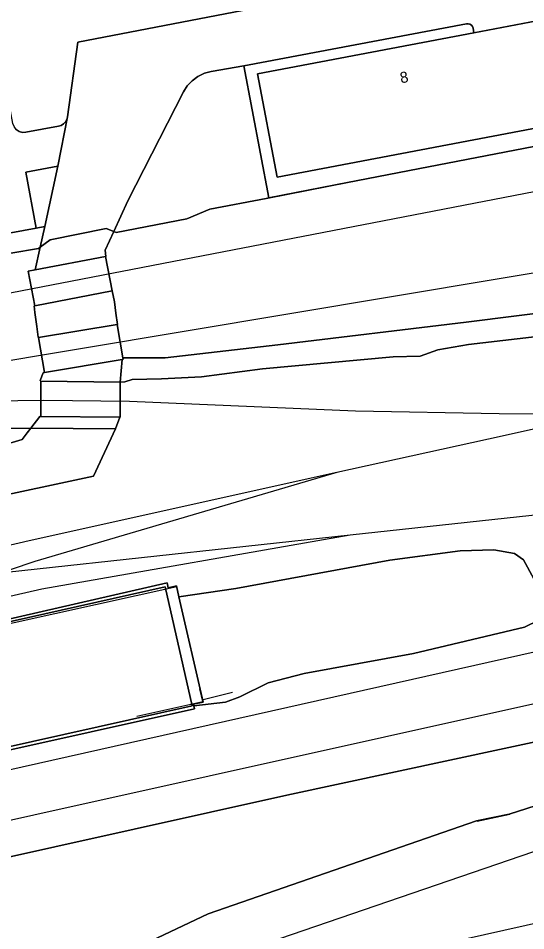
# Model space of a CAD drawing. Extents: x 161477 to 163040, y 383680 to 384871.
# Drawn here: x 161762.8 to 161808.8, y 383823.4 to 383906.2 of the extents above; entities that cross this region are included whole.
import ezdxf

# ---------------------------------------------------------------- set-up
doc = ezdxf.new("R2010")
doc.units = 0
for name, color, linetype in [('IMGEO_Erf', 7, 'Continuous'), ('IMGEO_Groenvoorziening', 7, 'Continuous'), ('IMGEO_Hek', 7, 'Continuous'), ('IMGEO_Overweg_gesloten', 7, 'Continuous'), ('IMGEO_Pand', 7, 'Continuous'), ('IMGEO_Pand_nummerreeks', 7, 'Continuous'), ('IMGEO_Rijbaan_lokaal_open', 7, 'Continuous'), ('IMGEO_Spoor', 7, 'Continuous'), ('IMGEO_Spoorbaan_halfverhard', 7, 'Continuous'), ('IMGEO_Terreindeel_halfverhard', 7, 'Continuous'), ('IMGEO_Terreindeel_onvherhard', 7, 'Continuous'), ('IMGEO_Terreindeel_open', 7, 'Continuous'), ('IMGEO_Voetpad_open', 7, 'Continuous')]:
    doc.layers.add(name, color=color, linetype=linetype)

msp = doc.modelspace()

# ---------------------------------------------------------------- linework, layer by layer
at = {"layer": 'IMGEO_Erf'}
msp.add_lwpolyline([(161767.236, 383897.259), (161767.174, 383897.026), (161767.051, 383896.805), (161766.874, 383896.62), (161766.66, 383896.487), (161766.43, 383896.415), (161763.462, 383895.858), (161763.165, 383895.847), (161762.856, 383895.934), (161762.584, 383896.12), (161762.392, 383896.376), (161762.294, 383896.657), (161761.349, 383901.699), (161722.371, 383894.524), (161723.464, 383887.761), (161723.688, 383886.379), (161724.738, 383879.878), (161764.405, 383887.161), (161763.458, 383892.256), (161766.369, 383892.797)], close=True, dxfattribs=at)
at = {"layer": 'IMGEO_Groenvoorziening'}
msp.add_lwpolyline([(161762.584, 383896.12), (161762.856, 383895.934), (161763.165, 383895.847), (161763.462, 383895.858), (161766.43, 383896.415), (161766.66, 383896.487), (161766.874, 383896.62), (161767.051, 383896.805), (161767.174, 383897.026), (161767.236, 383897.259), (161768.191, 383904.054), (161805.301, 383911.22)], dxfattribs=at)
for points in [[(161785.514, 383889.906), (161783.238, 383901.895), (161780.285, 383901.383), (161779.67, 383901.218), (161779.081, 383900.935), (161778.55, 383900.543), (161778.105, 383900.064), (161777.765, 383899.525), (161772.727, 383889.643), (161771.445, 383886.853), (161771.671, 383886.768), (161778.078, 383888.005), (161780.165, 383888.875), (161785.283, 383889.861)], [(161765.176, 383887.303), (161764.405, 383887.161), (161724.738, 383879.878), (161723.688, 383886.379), (161722.971, 383886.245), (161716.299, 383884.995), (161716.246, 383885.278), (161715.329, 383885.106), (161716.52, 383877.272), (161722.035, 383878.5), (161722.078, 383878.305), (161733.201, 383880.57), (161733.173, 383880.718), (161759.825, 383885.639), (161762.093, 383884.874), (161764.602, 383885.314), (161764.771, 383885.439)]]:
    msp.add_lwpolyline(points, close=True, dxfattribs=at)
at = {"layer": 'IMGEO_Hek'}
for points in [[(161722.078, 383878.305), (161733.201, 383880.57), (161733.173, 383880.718), (161759.825, 383885.639), (161762.093, 383884.874), (161764.602, 383885.314), (161764.771, 383885.439), (161765.685, 383886.113), (161770.75, 383887.114), (161771.445, 383886.853), (161771.671, 383886.768), (161778.078, 383888.005), (161780.165, 383888.875), (161785.283, 383889.861), (161792.641, 383891.294), (161800.007, 383892.712), (161812.228, 383895.079), (161824.037, 383897.352)], [(161729.828, 383842.456), (161729.416, 383844.078), (161732.581, 383844.772), (161777.154, 383854.64)], [(161773.549, 383842.85), (161779.526, 383844.173), (161779.263, 383845.35)], [(161782.207, 383845.009), (161779.557, 383844.346)], [(161804.433, 383833.315), (161807.374, 383833.945)]]:
    msp.add_lwpolyline(points, dxfattribs=at)
at = {"layer": 'IMGEO_Overweg_gesloten'}
for points in [[(161764.322, 383883.369), (161763.665, 383883.243), (161764.27, 383880.1), (161771.309, 383881.454), (161770.704, 383884.597)], [(161771.759, 383878.4), (161764.625, 383877.218), (161765.165, 383874.05), (161772.192, 383875.249), (161772.294, 383875.266), (161772.275, 383875.377)], [(161772.009, 383869.987), (161772.035, 383873.175), (161764.837, 383873.281), (161764.81, 383870.045), (161771.994, 383869.987)]]:
    msp.add_lwpolyline(points, close=True, dxfattribs=at)
at = {"layer": 'IMGEO_Pand'}
for points in [[(161804.125, 383904.891), (161784.496, 383901.165), (161786.276, 383891.788), (161823.722, 383898.897), (161822.28, 383906.491), (161810.184, 383904.195), (161809.846, 383905.977)], [(161778.557, 383843.801), (161776.109, 383854.605), (161755.704, 383850.023), (161755.755, 383849.764), (161732.215, 383844.538), (161734.605, 383834.247), (161758.264, 383839.562), (161758.339, 383839.278)]]:
    msp.add_lwpolyline(points, close=True, dxfattribs=at)
at = {"layer": 'IMGEO_Rijbaan_lokaal_open'}
msp.add_lwpolyline([(161805.301, 383911.22), (161768.191, 383904.054), (161767.236, 383897.259), (161766.369, 383892.797), (161765.176, 383887.303), (161764.771, 383885.439), (161765.685, 383886.113), (161770.75, 383887.114), (161771.445, 383886.853), (161772.727, 383889.643), (161777.765, 383899.525), (161778.105, 383900.064), (161778.55, 383900.543), (161779.081, 383900.935), (161779.67, 383901.218), (161780.285, 383901.383), (161783.238, 383901.895), (161803.46, 383905.713), (161803.609, 383905.719), (161803.763, 383905.676), (161803.899, 383905.583), (161803.996, 383905.455), (161804.045, 383905.315), (161804.125, 383904.891), (161809.846, 383905.977)], dxfattribs=at)
at = {"layer": 'IMGEO_Spoor'}
for points in [[(162082.223, 383940.616), (162067.156, 383939.077), (162060.654, 383938.31), (162050.143, 383936.843), (162039.55, 383934.981), (161761.259, 383881.105), (161737.229, 383876.551), (161717.526, 383872.756)], [(161940.49, 383907.276), (161906.48, 383899.966), (161883.869, 383895.635), (161863.414, 383892.09), (161749.217, 383872.993)], [(162080.398, 383888.27), (162044.958, 383880.311), (162029.101, 383876.523), (161994.284, 383867.842), (161928.357, 383851.121), (161903.852, 383845.057), (161837.128, 383830.061), (161814.392, 383825.096), (161790.225, 383819.662), (161771.313, 383815.494)], [(161824.986, 383872.35), (161806.689, 383868.266)], [(161806.429, 383870.315), (161793.378, 383870.54), (161772.884, 383871.416), (161765.082, 383871.527), (161757.988, 383871.43), (161749.52, 383871.15)], [(161825.177, 383870.214), (161806.429, 383870.315)], [(161903.397, 383869.387), (161898.271, 383868.21), (161875.366, 383863.331), (161858.277, 383859.477), (161835.183, 383854.417), (161757.446, 383836.94), (161730.852, 383831.025)], [(161806.689, 383868.266), (161791.676, 383864.969)], [(161876.441, 383868.342), (161792.911, 383859.296)], [(161904.374, 383864.997), (161886.895, 383861.275), (161827.55, 383847.971), (161732.614, 383826.843)], [(161791.676, 383864.969), (161763.769, 383858.759)], [(161791.676, 383864.969), (161764.271, 383856.91)], [(161904.907, 383863.206), (161784.263, 383821.871), (161770.675, 383817.305)], [(161763.769, 383858.759), (161757.11, 383857.231)], [(161792.911, 383859.296), (161764.487, 383856.214)], [(161792.911, 383859.296), (161764.901, 383854.376)], [(161764.271, 383856.91), (161757.708, 383854.689)], [(161764.487, 383856.214), (161757.489, 383855.453)], [(161764.901, 383854.376), (161758.132, 383852.854)]]:
    msp.add_lwpolyline(points, dxfattribs=at)
at = {"layer": 'IMGEO_Spoorbaan_halfverhard'}
for points in [[(161812.228, 383895.079), (161800.007, 383892.712), (161792.641, 383891.294), (161785.514, 383889.906), (161785.283, 383889.861), (161780.165, 383888.875), (161778.078, 383888.005), (161771.671, 383886.768), (161771.445, 383886.853), (161770.667, 383885.158), (161770.72, 383884.6), (161770.704, 383884.597), (161771.309, 383881.454), (161771.506, 383880.462), (161771.617, 383879.447), (161771.79, 383878.405), (161771.759, 383878.4), (161772.275, 383875.377), (161772.348, 383875.385), (161773.116, 383875.388), (161776.108, 383875.392), (161786.324, 383876.575), (161803.439, 383878.619), (161831.301, 383882.13)], [(161756.314, 383868.919), (161763.91, 383869.004), (161764.726, 383870.046), (161764.81, 383870.045), (161764.837, 383873.281), (161764.753, 383873.313), (161765.022, 383874.025), (161765.165, 383874.05), (161764.625, 383877.218), (161764.585, 383877.26), (161764.452, 383878.231), (161764.268, 383879.505), (161764.231, 383880.093), (161764.27, 383880.1), (161763.665, 383883.243), (161764.322, 383883.369), (161764.771, 383885.439), (161764.602, 383885.314), (161762.093, 383884.874)], [(161835.851, 383880.353), (161803.644, 383876.596), (161800.862, 383876.121), (161799.248, 383875.526), (161796.787, 383875.47), (161784.952, 383874.377), (161779.404, 383873.666), (161775.777, 383873.479), (161773.1, 383873.431), (161772.45, 383873.203), (161772.035, 383873.175), (161772.009, 383869.987), (161771.994, 383869.987), (161771.593, 383868.932), (161769.615, 383864.652), (161727.031, 383855.539)], [(161735.246, 383845.563), (161776.294, 383854.953), (161776.381, 383854.51), (161777.137, 383854.673), (161777.363, 383853.696), (161782.519, 383854.442), (161796.5, 383857.009), (161802.891, 383857.878), (161805.928, 383857.97), (161807.801, 383857.637), (161808.614, 383857.045), (161809.551, 383855.315)], [(161810.031, 383851.558), (161808.72, 383850.932), (161798.631, 383848.548), (161788.718, 383846.733), (161785.47, 383845.876), (161782.893, 383844.62), (161781.595, 383844.133), (161778.695, 383843.791), (161778.756, 383843.512), (161741.226, 383835.179), (161731.161, 383832.867), (161731.925, 383829.388), (161732.148, 383828.375), (161732.75, 383828.509), (161733.446, 383825.38), (161733.249, 383825.336), (161734.085, 383823.354), (161741.915, 383825.707), (161752.2, 383827.921), (161787.153, 383835.688), (161840.96, 383847.258)], [(161832.593, 383842.069), (161807.325, 383833.951), (161804.37, 383833.339), (161779.997, 383824.916), (161774.846, 383822.458), (161769.612, 383820.731), (161764.048, 383819.188), (161763.694, 383818.226), (161749.23, 383813.874), (161748.36, 383814.578), (161739.097, 383812.525), (161738.8, 383812.167), (161754.197, 383775.636), (161754.401, 383775.133), (161754.589, 383774.631), (161754.766, 383774.117), (161758.469, 383762.883)]]:
    msp.add_lwpolyline(points, dxfattribs=at)
at = {"layer": 'IMGEO_Terreindeel_halfverhard'}
for points in [[(161831.301, 383882.13), (161803.439, 383878.619), (161786.324, 383876.575), (161776.108, 383875.392), (161773.116, 383875.388), (161772.348, 383875.385), (161772.275, 383875.377), (161772.294, 383875.266), (161772.192, 383875.249), (161772.035, 383873.175), (161772.45, 383873.203), (161773.1, 383873.431), (161775.777, 383873.479), (161779.404, 383873.666), (161784.952, 383874.377), (161796.787, 383875.47), (161799.248, 383875.526), (161800.862, 383876.121), (161803.644, 383876.596), (161835.851, 383880.353)], [(161809.551, 383855.315), (161808.614, 383857.045), (161807.801, 383857.637), (161805.928, 383857.97), (161802.891, 383857.878), (161796.5, 383857.009), (161782.519, 383854.442), (161777.363, 383853.696), (161779.565, 383844.138), (161778.662, 383843.942), (161778.695, 383843.791), (161781.595, 383844.133), (161782.893, 383844.62), (161785.47, 383845.876), (161788.718, 383846.733), (161798.631, 383848.548), (161808.72, 383850.932), (161810.031, 383851.558)]]:
    msp.add_lwpolyline(points, dxfattribs=at)
msp.add_lwpolyline([(161720.058, 383863.522), (161720.195, 383862.93), (161720.714, 383863.043), (161725.104, 383864.003), (161730.693, 383862.811), (161734.603, 383862.221), (161737.924, 383862.127), (161738.563, 383862.213), (161740.728, 383862.504), (161753.212, 383865.309), (161754.366, 383865.403), (161759.943, 383867.044), (161763.142, 383867.985), (161763.59, 383868.567), (161763.91, 383869.004), (161756.314, 383868.919), (161736.614, 383867.965), (161729.676, 383867.336), (161724.83, 383866.636), (161722.094, 383866.153), (161719.978, 383866.346), (161718.986, 383866.202), (161719.067, 383865.837), (161719.606, 383863.417)], close=True, dxfattribs=at)
at = {"layer": 'IMGEO_Terreindeel_onvherhard'}
msp.add_lwpolyline([(161738.8, 383812.167), (161739.097, 383812.525), (161748.36, 383814.578), (161749.23, 383813.874), (161763.694, 383818.226), (161764.048, 383819.188), (161769.612, 383820.731), (161774.846, 383822.458), (161779.997, 383824.916), (161804.37, 383833.339), (161807.325, 383833.951), (161832.593, 383842.069), (161841.369, 383846.435), (161840.96, 383847.258), (161787.153, 383835.688), (161752.2, 383827.921), (161741.915, 383825.707), (161734.085, 383823.354)], close=True, dxfattribs=at)
at = {"layer": 'IMGEO_Terreindeel_open'}
msp.add_lwpolyline([(161810.288, 383906.061), (161809.846, 383905.977), (161810.184, 383904.195), (161822.28, 383906.491), (161823.722, 383898.897), (161786.276, 383891.788), (161784.496, 383901.165), (161804.125, 383904.891), (161804.045, 383905.315), (161803.996, 383905.455), (161803.899, 383905.583), (161803.763, 383905.676), (161803.609, 383905.719), (161803.46, 383905.713), (161783.238, 383901.895), (161785.514, 383889.906), (161792.641, 383891.294), (161800.007, 383892.712), (161812.228, 383895.079), (161824.037, 383897.352), (161831.558, 383898.701), (161834.037, 383899.213), (161860.382, 383904.241), (161881.519, 383908.403)], dxfattribs=at)
for points in [[(161764.322, 383883.369), (161770.704, 383884.597), (161770.72, 383884.6), (161770.667, 383885.158), (161771.445, 383886.853), (161770.75, 383887.114), (161765.685, 383886.113), (161764.771, 383885.439)], [(161764.231, 383880.093), (161764.268, 383879.505), (161764.452, 383878.231), (161764.585, 383877.26), (161764.625, 383877.218), (161771.759, 383878.4), (161771.79, 383878.405), (161771.617, 383879.447), (161771.506, 383880.462), (161771.309, 383881.454), (161764.27, 383880.1)], [(161765.165, 383874.05), (161765.022, 383874.025), (161764.753, 383873.313), (161764.837, 383873.281), (161772.035, 383873.175), (161772.192, 383875.249)], [(161764.81, 383870.045), (161764.726, 383870.046), (161763.91, 383869.004), (161771.593, 383868.932), (161771.994, 383869.987)], [(161725.104, 383864.003), (161725.748, 383861.057), (161727.031, 383855.539), (161769.615, 383864.652), (161771.593, 383868.932), (161763.91, 383869.004), (161763.59, 383868.567), (161763.142, 383867.985), (161759.943, 383867.044), (161754.366, 383865.403), (161753.212, 383865.309), (161740.728, 383862.504), (161738.563, 383862.213), (161737.924, 383862.127), (161734.603, 383862.221), (161730.693, 383862.811)], [(161730.111, 383832.783), (161731.13, 383833.007), (161731.161, 383832.867), (161741.226, 383835.179), (161778.756, 383843.512), (161778.695, 383843.791), (161778.662, 383843.942), (161779.565, 383844.138), (161777.363, 383853.696), (161777.137, 383854.673), (161776.381, 383854.51), (161776.294, 383854.953), (161735.246, 383845.563), (161729.677, 383844.319), (161729.602, 383844.655), (161725.494, 383843.737)], [(161778.557, 383843.801), (161758.339, 383839.278), (161758.264, 383839.562), (161734.605, 383834.247), (161732.215, 383844.538), (161755.755, 383849.764), (161755.704, 383850.023), (161776.109, 383854.605)]]:
    msp.add_lwpolyline(points, close=True, dxfattribs=at)
at = {"layer": 'IMGEO_Voetpad_open'}
msp.add_lwpolyline([(161766.369, 383892.797), (161763.458, 383892.256), (161764.405, 383887.161), (161765.176, 383887.303)], close=True, dxfattribs=at)

# ---------------------------------------------------------------- texts
at = {"layer": 'IMGEO_Pand_nummerreeks'}
msp.add_text('8', height=1, rotation=10.70285, dxfattribs=at).set_placement((161797.515, 383900.298))

doc.saveas('drawing.dxf')
